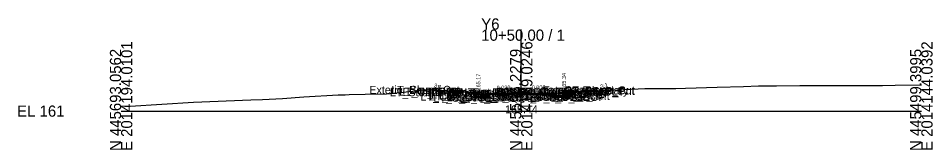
# Model space of a CAD drawing. Extents: x -26 to 203, y -10 to 4529.
# Drawn here: x -25.7 to 202.8, y 990.3 to 1023.3 of the extents above; entities that cross this region are included whole.
import ezdxf

# ---------------------------------------------------------------- set-up
doc = ezdxf.new("R2010")
doc.units = 0
for name, color, linetype in [('Default', 7, 'Continuous'), ('Exist CMT Pavement', 7, 'Continuous'), ('Exist Cross Section Cell', 7, 'Continuous'), ('Exist XS Center Line Elevation Label', 7, 'Continuous'), ('Exist XS Ground Line', 7, 'Continuous'), ('Prop CMT Conc Surface', 7, 'Continuous'), ('Prop CMT Concrete Structures', 7, 'Continuous'), ('Prop CMT Pvmt Course 1', 7, 'Continuous'), ('Prop CMT Pvmt Course 1 CG', 7, 'Continuous'), ('Prop CMT Pvmt Course 2', 7, 'Continuous'), ('Prop CMT Pvmt Course 3', 7, 'Continuous'), ('Prop CMT Pvmt Surface', 7, 'Continuous'), ('Prop CMT Pvmt Wedge Surface 1', 7, 'Continuous'), ('Prop CMT Pvmt Wedge Surface 2', 7, 'Continuous'), ('Prop CMT Slope Grass', 7, 'Continuous'), ('Prop CMT Subgrade Earthwork', 7, 'Continuous'), ('Prop XS Earthwork Shape', 7, 'Continuous'), ('Prop XS Hydro Elevations', 7, 'Continuous'), ('Prop XS SE Text', 7, 'Continuous'), ('Prop XS Side Slope Text', 7, 'Continuous'), ('Scratch_Level_0', 7, 'Continuous')]:
    doc.layers.add(name, color=color, linetype=linetype)

msp = doc.modelspace()

# ---------------------------------------------------------------- linework, layer by layer
at = {"layer": 'Exist CMT Pavement'}
msp.add_lwpolyline([(92.28, 1004.26), (95.2, 1004.31), (100, 1004.44), (101.34, 1004.48), (104.17, 1004.41), (107.67, 1004.37)], dxfattribs=at)
at = {"layer": 'Exist Cross Section Cell'}
for p, q in [((100, 1000), (100, 1020.44)), ((0, 1000), (100, 1000)), ((100, 1000), (200, 1000))]:
    msp.add_line(p, q, dxfattribs=at)
at = {"layer": 'Exist XS Ground Line'}
msp.add_lwpolyline([(0.9, 1001.12), (2.3, 1001.26), (18.07, 1002.21), (32.4, 1002.81), (35.35, 1002.94), (40.35, 1003.2), (45.68, 1003.62), (54.27, 1004.06), (56, 1004.12), (57.03, 1004.15), (60.99, 1004.21), (66.33, 1004.33), (68.19, 1004.53), (76.66, 1005.39), (83.19, 1005.06), (91.5, 1004.25), (95.2, 1004.31), (100, 1004.44), (101.34, 1004.48), (104.17, 1004.41), (108.76, 1004.36), (116.93, 1005.02), (117.42, 1005.04), (130.92, 1005.67), (138.63, 1005.7), (141.05, 1005.77), (148.96, 1006.01), (155.55, 1006.18), (159.29, 1006.3), (163.76, 1006.37), (169.62, 1006.41), (171.97, 1006.45), (179.95, 1006.39), (181.08, 1006.38), (190.28, 1006.43), (193.48, 1006.49), (200, 1006.6)], dxfattribs=at)
at = {"layer": 'Prop CMT Conc Surface'}
for points in [[(89.28, 1004.17), (89.28, 1004.67), (88.78, 1004.67)], [(91.28, 1004.29), (89.28, 1004.17)], [(108.67, 1004.43), (110.67, 1004.34)], [(110.67, 1004.34), (110.68, 1004.84), (111.18, 1004.84)]]:
    msp.add_lwpolyline(points, dxfattribs=at)
at = {"layer": 'Prop CMT Concrete Structures'}
for points in [[(91.28, 1004.29), (89.28, 1004.17), (89.28, 1004.67), (88.78, 1004.67)], [(88.78, 1004.67), (88.78, 1003.66), (91.28, 1003.71)], [(91.28, 1003.71), (91.28, 1004.29)], [(108.67, 1004.43), (110.67, 1004.34), (110.68, 1004.84), (111.18, 1004.84)], [(111.18, 1004.84), (111.17, 1003.83), (108.67, 1003.84)], [(108.67, 1003.84), (108.67, 1004.43)]]:
    msp.add_lwpolyline(points, dxfattribs=at)
at = {"layer": 'Prop CMT Pvmt Course 1'}
for p in [(92.28, 1004.19), (107.67, 1004.31)]:
    msp.add_line(p, (100, 1004.34), dxfattribs=at)
for points in [[(100, 1004.47), (91.28, 1004.29)], [(91.28, 1004.29), (91.28, 1004.04)], [(91.28, 1004.04), (92.28, 1004.06)], [(92.28, 1004.06), (92.28, 1004.19)], [(100, 1004.22), (100, 1004.47)], [(100, 1004.22), (100, 1004.47)], [(100, 1004.47), (108.67, 1004.43)], [(107.67, 1004.18), (107.67, 1004.31)], [(108.67, 1004.18), (107.67, 1004.18)], [(108.67, 1004.43), (108.67, 1004.18)]]:
    msp.add_lwpolyline(points, dxfattribs=at)
msp.add_lwpolyline([(100, 1004.22), (100, 1004.34), (100, 1004.34), (100, 1004.22)], close=True, dxfattribs=at)
msp.add_lwpolyline([(100, 1004.22), (100, 1004.34), (100, 1004.34), (100, 1004.22)], close=True, dxfattribs=at)
at = {"layer": 'Prop CMT Pvmt Course 1 CG'}
for points in [[(91.28, 1003.71), (88.28, 1003.65), (87.98, 1003.35)], [(87.98, 1003.35), (91.28, 1003.42)], [(91.28, 1003.42), (91.28, 1003.71)], [(108.67, 1003.84), (111.67, 1003.83), (111.97, 1003.54)], [(108.67, 1003.55), (108.67, 1003.84)], [(111.97, 1003.54), (108.67, 1003.55)]]:
    msp.add_lwpolyline(points, dxfattribs=at)
at = {"layer": 'Prop CMT Pvmt Course 2'}
for points in [[(92.28, 1004.06), (91.28, 1004.04)], [(91.28, 1004.04), (91.28, 1003.79)], [(91.28, 1003.79), (92.28, 1003.81)], [(92.28, 1003.81), (92.28, 1004.06)], [(107.67, 1004.18), (108.67, 1004.18)], [(107.67, 1003.93), (107.67, 1004.18)], [(108.67, 1003.93), (107.67, 1003.93)], [(108.67, 1004.18), (108.67, 1003.93)]]:
    msp.add_lwpolyline(points, dxfattribs=at)
at = {"layer": 'Prop CMT Pvmt Course 3'}
for points in [[(92.28, 1003.81), (91.28, 1003.79)], [(91.28, 1003.79), (91.28, 1003.42)], [(91.28, 1003.42), (92.28, 1003.44)], [(92.28, 1003.44), (92.28, 1003.81)], [(107.67, 1003.93), (108.67, 1003.93)], [(107.67, 1003.56), (107.67, 1003.93)], [(108.67, 1003.55), (107.67, 1003.56)], [(108.67, 1003.93), (108.67, 1003.55)]]:
    msp.add_lwpolyline(points, dxfattribs=at)
at = {"layer": 'Prop CMT Pvmt Surface'}
for points in [[(100, 1004.47), (91.28, 1004.29)], [(100, 1004.47), (108.67, 1004.43)]]:
    msp.add_lwpolyline(points, dxfattribs=at)
at = {"layer": 'Prop CMT Pvmt Wedge Surface 1'}
for q in [(92.28, 1004.19), (107.67, 1004.31)]:
    msp.add_line((100, 1004.34), q, dxfattribs=at)
for points in [[(92.28, 1004.19), (92.28, 1004.06)], [(107.67, 1004.31), (107.67, 1004.18)]]:
    msp.add_lwpolyline(points, dxfattribs=at)
at = {"layer": 'Prop CMT Pvmt Wedge Surface 2'}
for q in [(91.28, 1004.04), (108.67, 1004.18)]:
    msp.add_line((100, 1004.22), q, dxfattribs=at)
at = {"layer": 'Prop CMT Slope Grass'}
for points in [[(88.78, 1004.67), (79.28, 1004.86), (77.9, 1005.33)], [(111.18, 1004.84), (120.68, 1005.03), (121.24, 1005.22)]]:
    msp.add_lwpolyline(points, dxfattribs=at)
at = {"layer": 'Prop CMT Subgrade Earthwork'}
for p, q in [((92.28, 1003.44), (92.28, 1004.26)), ((107.67, 1003.56), (107.67, 1004.37))]:
    msp.add_line(p, q, dxfattribs=at)
for points in [[(91.28, 1003.42), (87.98, 1003.35), (86.62, 1004.72)], [(92.28, 1003.44), (91.28, 1003.42)], [(107.67, 1003.56), (108.67, 1003.55)], [(108.67, 1003.55), (111.97, 1003.54), (113.31, 1004.88)]]:
    msp.add_lwpolyline(points, dxfattribs=at)
at = {"layer": 'Prop XS Earthwork Shape'}
for points in [[(77.9, 1005.33), (83.19, 1005.06), (86.73, 1004.72), (86.62, 1004.72), (79.28, 1004.86)], [(86.73, 1004.72), (86.62, 1004.72), (87.98, 1003.35), (91.28, 1003.42), (92.28, 1003.44), (92.28, 1004.26), (91.5, 1004.25), (91.28, 1004.27), (91.28, 1003.71), (88.78, 1003.66), (88.78, 1004.51)], [(88.78, 1004.51), (88.78, 1003.66), (91.28, 1003.71), (91.28, 1004.27), (91.11, 1004.28), (89.28, 1004.17), (89.28, 1004.46)], [(89.28, 1004.46), (91.11, 1004.28), (89.28, 1004.17)], [(100.84, 1004.47), (101.34, 1004.48), (102.16, 1004.46)], [(100.84, 1004.47), (102.16, 1004.46), (101.34, 1004.48)], [(111.17, 1004.56), (113.15, 1004.72), (111.97, 1003.54), (108.67, 1003.55), (107.67, 1003.56), (107.67, 1004.37), (108.67, 1004.36), (108.67, 1003.84), (111.17, 1003.83)], [(109.25, 1004.4), (110.67, 1004.34), (110.67, 1004.52), (111.17, 1004.56), (111.17, 1003.83), (108.67, 1003.84), (108.67, 1004.36), (108.76, 1004.36)], [(109.25, 1004.4), (110.67, 1004.34), (110.67, 1004.52)], [(113.15, 1004.72), (113.31, 1004.88), (115.81, 1004.93)], [(115.81, 1004.93), (116.93, 1005.02), (117.42, 1005.04), (121.24, 1005.22), (120.68, 1005.03)]]:
    msp.add_lwpolyline(points, close=True, dxfattribs=at)

# ---------------------------------------------------------------- texts
at = {"layer": 'Default'}
msp.add_text('-', height=0.0001, dxfattribs=at).set_placement((0, 1000))
at = {"layer": 'Exist Cross Section Cell'}
for s, p in [('Y6', (90, 1020.44)), ('10+50.00 / 1', (90, 1017.64)), ('EL 161', (-26, 998.6))]:
    msp.add_text(s, height=2.8, dxfattribs=at).set_placement(p)
for s, p in [('E 2014194.0101', (2.8, 990)), ('E 2014169.0246', (102.8, 990)), ('E 2014144.0392', (202.8, 990)), ('N 445693.0562', (0, 990)), ('N 445596.2279', (100, 990)), ('N 445499.3995', (200, 990))]:
    msp.add_text(s, height=2.8, rotation=90, dxfattribs=at).set_placement(p)
at = {"layer": 'Exist XS Center Line Elevation Label'}
msp.add_text('165.44', height=2, dxfattribs=at).set_placement((95.96, 999.44))
at = {"layer": 'Prop XS Hydro Elevations'}
for s, p in [('165.17', (89.78, 1005.17)), ('165.34', (111.17, 1005.34))]:
    msp.add_text(s, height=1, rotation=90, dxfattribs=at).set_placement(p)
at = {"layer": 'Prop XS SE Text'}
for s, rotation, p in [('0.020', 1.1458, (93.87, 1005.35)), ('0.005', 359.7304, (102.61, 1005.46))]:
    msp.add_text(s, height=1, rotation=rotation, dxfattribs=at).set_placement(p)
at = {"layer": 'Prop XS Side Slope Text'}
for rotation, p in [(341.5652, (78.07, 1006.06)), (18.4332, (119.97, 1005.58))]:
    msp.add_text('3:1', height=1, rotation=rotation, dxfattribs=at).set_placement(p)
at = {"layer": 'Scratch_Level_0'}
for s, p in [('Exterior Boundary', (62.04, 1004.33)), ('LT_Sub_Trench_Out_DLT', (67.19, 1003.72)), ('LT_Slope_Cut', (67.53, 1004.33)), ('LT_CSLP_Pnt', (69.45, 1003.86)), ('LT_CG_Top_Face', (76.54, 1003.67)), ('LT_CG_Top_BOC', (77.06, 1003.67)), ('RT_Sub_Trench_Out_DLT', (93.83, 1003.88)), ('RT_CG_Top_Face', (97.89, 1003.84)), ('RT_CG_Top_BOC', (99.41, 1003.84)), ('Exterior Boundary', (105.38, 1004.22)), ('RT_CSLP_Pnt', (110.8, 1004.03)), ('RT_Slope_Cut', (110.83, 1004.22)), ('LT_CG1_Shelf_Out', (74.83, 1002.65)), ('LT_CG_Bot_BOC', (77.1, 1002.66)), ('LT_CG_Top_Gut', (77.52, 1003.17)), ('LT_Sub_OEOP', (78.09, 1002.35)), ('LT_CG_Bot_IE', (81.19, 1002.71)), ('LT_Sub_OEOT', (81.36, 1002.42)), ('LT_PV2_OEOT', (81.45, 1003.04)), ('LT_PV3_OEOT', (81.45, 1002.79)), ('LT_PV1_OEOT', (82.02, 1003.29)), ('RT_Sub_OEEOP', (89.17, 1002.59)), ('LT_Sub_OEEOP', (89.21, 1002.59)), ('RT_PV2_OEEOP', (89.26, 1003.22)), ('RT_PV3_OEEOP', (89.26, 1002.97)), ('LT_PV2_OEEOP', (89.31, 1003.22)), ('LT_PV3_OEEOP', (89.31, 1002.97)), ('RT_PV1_OEEOP', (89.83, 1003.34)), ('LT_PV1_OEEOP', (89.87, 1003.34)), ('RT_PV2_IEEOP', (89.91, 1003.22)), ('LT_PV2_IEEOP', (89.95, 1003.22)), ('RT_PV1_IEEOP', (90.47, 1003.34)), ('LT_PV1_IEEOP', (90.52, 1003.34)), ('PV2_PGL', (93.91, 1003.22)), ('PV1_PGL', (94.47, 1003.47)), ('RT_CG1_Shelf_Out', (98.18, 1002.83)), ('RT_CG_Bot_IE', (98.54, 1002.84)), ('RT_Sub_OEOT', (98.71, 1002.55)), ('RT_PV2_OEOT', (98.8, 1003.18)), ('RT_PV3_OEOT', (98.8, 1002.93)), ('RT_CG_Top_Gut', (98.86, 1003.34)), ('RT_PV1_OEOT', (99.37, 1003.43)), ('RT_CG_Bot_BOC', (99.44, 1002.83)), ('RT_Sub_OEOP', (102.03, 1002.54))]:
    msp.add_text(s, height=2, dxfattribs=at).set_placement(p)

doc.saveas('drawing.dxf')
